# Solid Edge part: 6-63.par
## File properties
Author: Ashutosh-CADCIM
Template: Iso Metric Part.par
Last saved by: Ashutosh-CADCIM
Revision: 1
Application: Solid Edge
Accuracy: 0.990
Username: Ashutosh-CADCIM
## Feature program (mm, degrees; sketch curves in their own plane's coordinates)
sketch for "unnamed Protrusion 1" plane through (0, 0, 0) normal (0, 0, 1) x-axis (1, 0, 0)
  line (-20, -20) -> (130, -20)
  line (130, -20) -> (130, 80)
  line (130, 80) -> (-20, 80)
  line (-20, 80) -> (-20, -20)
  dimension (linear) = 20
  dimension (linear) = 130
extrude "unnamed Protrusion 1" add finite 20 along -normal
sketch for "unnamed Cutout 1" plane through (55, 30, 0) normal (0, 0, 1) x-axis (0, 1, 0)
  line (-35, 45) -> (-25, 45)
  line (-25, 45) -> (-25, 65)
  line (-25, 65) -> (-35, 65)
  line (-35, 65) -> (-35, 45)
extrude "unnamed Cutout 1" cut through along -normal
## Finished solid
Body 1: solid body, 10 faces, 24 edges, 16 vertices.
  Faces by surface: plane 10
  Edges by curve: line 24
Bounding box of the edges (mm): 150.000 x 100.000 x 20.000, from (-20, -20, -20) to (130, 80, 0).
Planar faces by outward normal: +x 2, +y 2, +z 1, -x 2, -y 2, -z 1
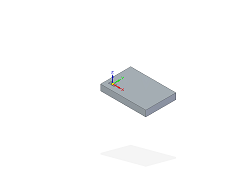
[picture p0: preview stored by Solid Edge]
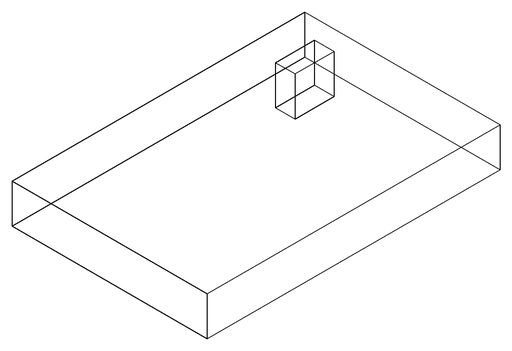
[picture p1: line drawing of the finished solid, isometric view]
